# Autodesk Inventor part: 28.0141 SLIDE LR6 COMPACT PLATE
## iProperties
Created: 2012-04
Part Number: 28.0141 SLIDE LR6 COMPACT PLATE
Document SubType Name: Modeling
Designer: Administrator
Density: 2.71 g/cm^3
Material: Aluminum-6061
Mass: 78.1578 g
Surface Area: 108.891 cm^2
Volume: 28.8405 cm^3
Author: Administrator
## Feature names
1. Extrusion1
2. Fillet1
3. Hole1
4. Extrusion2
5. Extrusion3
6. Hole2
